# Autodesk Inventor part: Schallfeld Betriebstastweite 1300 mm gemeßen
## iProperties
Shininess: 20.0
Length Units: 11269
Angle Units: 11279
Time Units: 11290
Mass Units: 11283
Length Display Precision: 2
Angle Display Precision: 2
Part Number: Schallfeld Betriebstastweite 1300 mm gemeßen
Material: Lexan (klar)
Document SubType Name: Modellieren
Description: Schallfeld 1,3 m
Checked By: Alves
Created: 2005-08
Designer: Klein
Manufacturer: Standard
Standards Organization: Custom
Density: 0.0
Volumn: 0.0
Area: 0.0
PropertySet Name: Model Information
Control State: 0
Master: False
Checked Out: False
Last Check In By: Kramp
Last Check In Date: 2005-08-11
ME: ST
Title: Schallfelder
Author: Klein
Comments: keine Bemerkung
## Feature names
1. Blindzone_Aussenglocke [Revolution]
